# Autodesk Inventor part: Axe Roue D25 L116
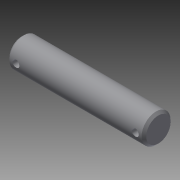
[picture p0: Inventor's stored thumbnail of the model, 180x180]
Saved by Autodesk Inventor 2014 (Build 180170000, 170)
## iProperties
Created: 2015-09
Part Number: Axe Roue D25 L116
Material: Générique
Document SubType Name: Modeling
Designer: OL
Density: 1 g/cm^3
Appearance: Par défaut
Author: OL
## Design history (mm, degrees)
sketch "Esquisse1"
  geometry: C1 r 12.5 at (0, 0); 1 further point
  constraints: 1 centre point, 1 coincident
  dimensions: "d0" = 25 diameter of C1
extrude "Extrusion1" new body sketch "Esquisse1" distance "d2" = 118; taper "d3" = 0 deg
chamfer "Chanfrein1" distance "d4" = 2; stored, may be unused: second distance "d5" = 2, angle "d6" = 45 deg
sketch "Esquisse2"
  geometry: C1 r 3 at (-110.5, 0); C2 r 3 at (-7.5, 0); 1 further point
  constraints: 2 centre point
  dimensions: "d7" = 6 diameter of C1; "d9" = 6 diameter of C2; "d10" = 7.5 distance of point (0, 0) C2.centre; "d11" = 110.5 distance of point (0, 0) C1.centre
extrude "Extrusion2" cut sketch "Esquisse2" stored distance "d13" = 100; taper "d14" = 0 deg
node "Solide1"
